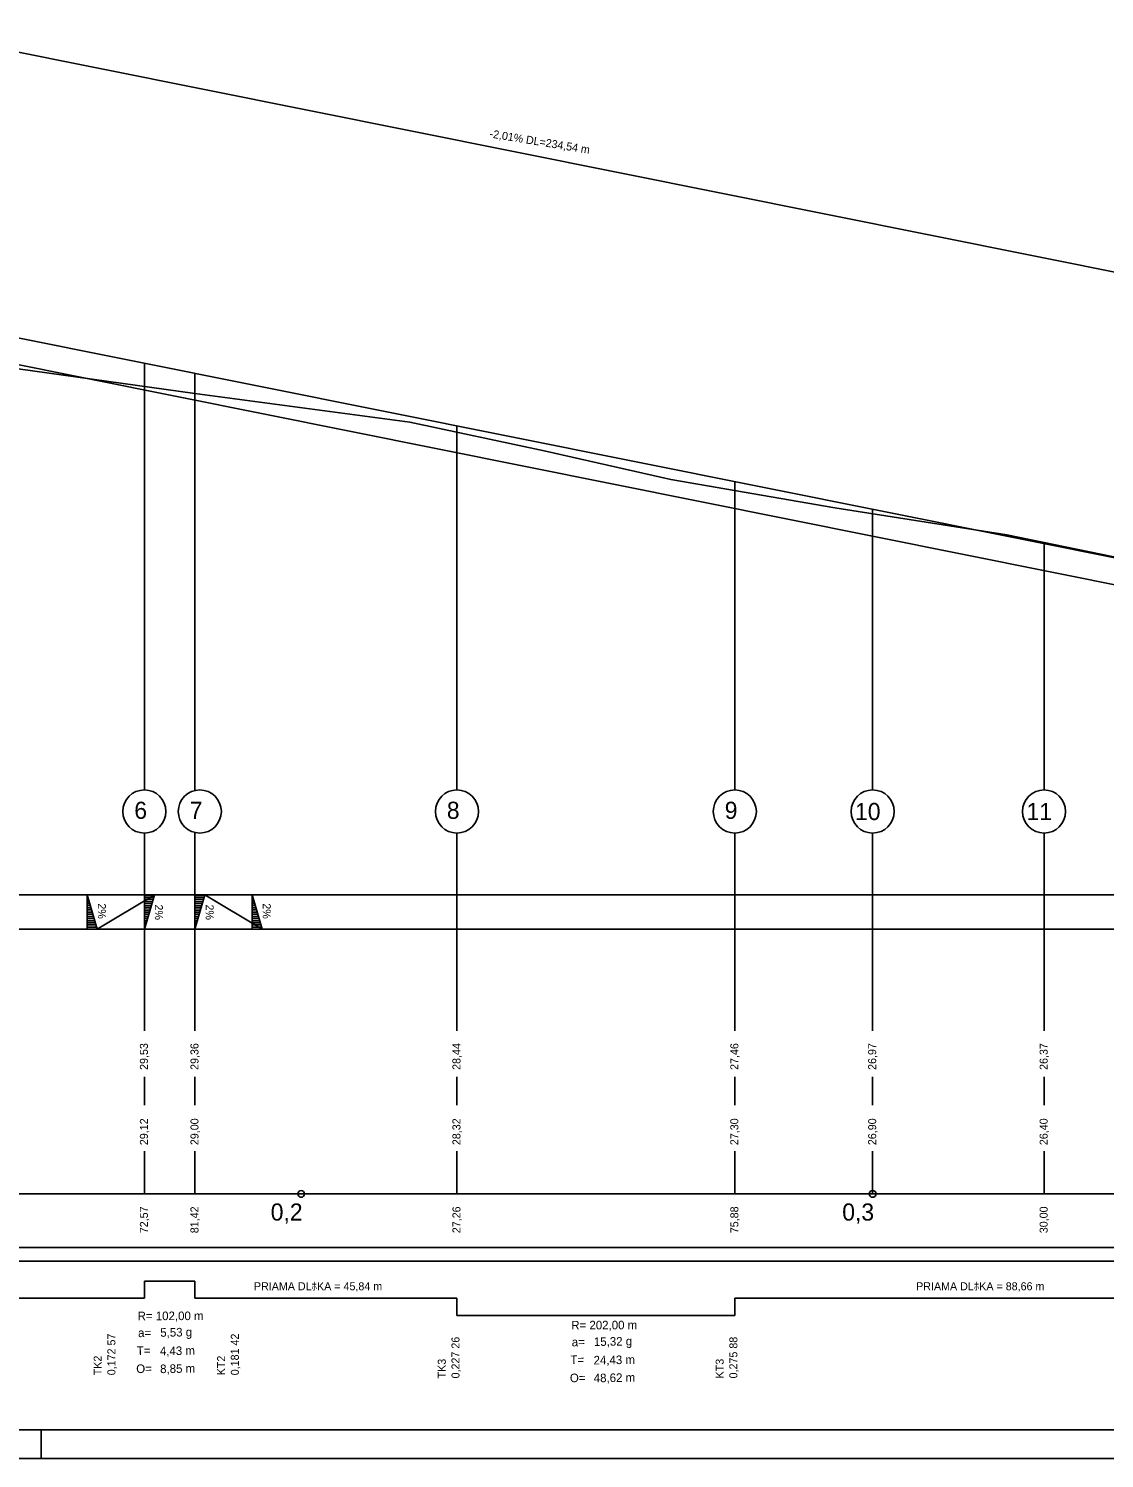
# Model space of a CAD drawing. Extents: x -499093 to -498463, y -1280289 to -1279879.
# Drawn here: x -498885.6 to -498697.4, y -1280289.4 to -1280039.2 of the extents above; entities that cross this region are included whole.
import ezdxf

# ---------------------------------------------------------------- set-up
doc = ezdxf.new("R2010")
doc.units = 0
for name, color, linetype in [('Vrstva 1', 7, 'Continuous'), ('Vrstva 11', 7, 'Continuous'), ('Vrstva 12', 7, 'Continuous'), ('Vrstva 13', 7, 'Continuous'), ('Vrstva 4', 7, 'Continuous'), ('Vrstva 5', 7, 'Continuous'), ('Vrstva 8', 7, 'Continuous')]:
    doc.layers.add(name, color=color, linetype=linetype)

msp = doc.modelspace()

# ---------------------------------------------------------------- linework, layer by layer
at = {"layer": 'Vrstva 1'}
for p, q in [((-499088.41, -1280284.38), (-498468.41, -1280284.38)), ((-498883.41, -1280284.38), (-498883.41, -1280289.38)), ((-499093.41, -1280289.38), (-498463.41, -1280289.38))]:
    msp.add_line(p, q, dxfattribs=at)
at = {"layer": 'Vrstva 11'}
for p, q in [((-498673.41, -1280136.31), (-498889.57, -1280092.93)), ((-498875.27, -1280191.18), (-498875.38, -1280191.18)), ((-498875.16, -1280191.56), (-498875.38, -1280191.56)), ((-498875.05, -1280191.93), (-498875.38, -1280191.93)), ((-498874.94, -1280192.31), (-498875.38, -1280192.31)), ((-498873.63, -1280196.81), (-498863.63, -1280190.81)), ((-498863.63, -1280190.82), (-498865.38, -1280190.82)), ((-498863.74, -1280191.2), (-498865.38, -1280191.2)), ((-498863.85, -1280191.57), (-498865.38, -1280191.57)), ((-498863.96, -1280191.95), (-498865.38, -1280191.95)), ((-498864.07, -1280192.32), (-498865.38, -1280192.32)), ((-498854.78, -1280190.82), (-498856.53, -1280190.82)), ((-498854.89, -1280191.2), (-498856.53, -1280191.2)), ((-498855, -1280191.57), (-498856.53, -1280191.57)), ((-498855.11, -1280191.95), (-498856.53, -1280191.95)), ((-498855.22, -1280192.32), (-498856.53, -1280192.32)), ((-498854.78, -1280190.81), (-498844.78, -1280196.81)), ((-498846.42, -1280191.18), (-498846.53, -1280191.18)), ((-498846.31, -1280191.56), (-498846.53, -1280191.56)), ((-498846.2, -1280191.93), (-498846.53, -1280191.93)), ((-498846.09, -1280192.31), (-498846.53, -1280192.31)), ((-498874.83, -1280192.68), (-498875.38, -1280192.68)), ((-498874.72, -1280193.06), (-498875.38, -1280193.06)), ((-498874.61, -1280193.43), (-498875.38, -1280193.43)), ((-498874.5, -1280193.81), (-498875.38, -1280193.81)), ((-498874.39, -1280194.18), (-498875.38, -1280194.18)), ((-498874.29, -1280194.56), (-498875.38, -1280194.56)), ((-498874.18, -1280194.93), (-498875.38, -1280194.93)), ((-498864.18, -1280192.7), (-498865.38, -1280192.7)), ((-498864.29, -1280193.07), (-498865.38, -1280193.07)), ((-498864.39, -1280193.45), (-498865.38, -1280193.45)), ((-498864.5, -1280193.82), (-498865.38, -1280193.82)), ((-498864.61, -1280194.2), (-498865.38, -1280194.2)), ((-498864.72, -1280194.57), (-498865.38, -1280194.57)), ((-498864.83, -1280194.95), (-498865.38, -1280194.95)), ((-498855.33, -1280192.7), (-498856.53, -1280192.7)), ((-498855.44, -1280193.07), (-498856.53, -1280193.07)), ((-498855.54, -1280193.45), (-498856.53, -1280193.45)), ((-498855.65, -1280193.82), (-498856.53, -1280193.82)), ((-498855.76, -1280194.2), (-498856.53, -1280194.2)), ((-498855.87, -1280194.57), (-498856.53, -1280194.57)), ((-498855.98, -1280194.95), (-498856.53, -1280194.95)), ((-498845.98, -1280192.68), (-498846.53, -1280192.68)), ((-498845.87, -1280193.06), (-498846.53, -1280193.06)), ((-498845.76, -1280193.43), (-498846.53, -1280193.43)), ((-498845.65, -1280193.81), (-498846.53, -1280193.81)), ((-498845.54, -1280194.18), (-498846.53, -1280194.18)), ((-498845.44, -1280194.56), (-498846.53, -1280194.56)), ((-498845.33, -1280194.93), (-498846.53, -1280194.93)), ((-498874.07, -1280195.31), (-498875.38, -1280195.31)), ((-498873.96, -1280195.68), (-498875.38, -1280195.68)), ((-498873.85, -1280196.06), (-498875.38, -1280196.06)), ((-498873.74, -1280196.43), (-498875.38, -1280196.43)), ((-498873.63, -1280196.81), (-498875.38, -1280196.81)), ((-498864.94, -1280195.32), (-498865.38, -1280195.32)), ((-498865.05, -1280195.7), (-498865.38, -1280195.7)), ((-498865.16, -1280196.07), (-498865.38, -1280196.07)), ((-498865.27, -1280196.45), (-498865.38, -1280196.45)), ((-498856.09, -1280195.32), (-498856.53, -1280195.32)), ((-498856.2, -1280195.7), (-498856.53, -1280195.7)), ((-498856.31, -1280196.07), (-498856.53, -1280196.07)), ((-498856.42, -1280196.45), (-498856.53, -1280196.45)), ((-498845.22, -1280195.31), (-498846.53, -1280195.31)), ((-498845.11, -1280195.68), (-498846.53, -1280195.68)), ((-498845, -1280196.06), (-498846.53, -1280196.06)), ((-498844.89, -1280196.43), (-498846.53, -1280196.43)), ((-498844.78, -1280196.81), (-498846.53, -1280196.81)), ((-499036.78, -1280243.11), (-498703.7, -1280243.11)), ((-499036.78, -1280243.11), (-498703.7, -1280243.11))]:
    msp.add_line(p, q, dxfattribs=at)
for points in [[(-498875.38, -1280196.81), (-498875.38, -1280190.81), (-498873.63, -1280196.81), (-498875.38, -1280196.81)], [(-498865.38, -1280190.81), (-498865.38, -1280196.81), (-498863.63, -1280190.81), (-498865.38, -1280190.81)], [(-498856.53, -1280190.81), (-498856.53, -1280196.81), (-498854.78, -1280190.81), (-498856.53, -1280190.81)], [(-498846.53, -1280196.81), (-498846.53, -1280190.81), (-498844.78, -1280196.81), (-498846.53, -1280196.81)]]:
    msp.add_lwpolyline(points, dxfattribs=at)
for centre in [(-498865.38, -1280176.21), (-498855.68, -1280176.21), (-498810.69, -1280176.21), (-498762.07, -1280176.21), (-498737.95, -1280176.21), (-498707.95, -1280176.21)]:
    msp.add_circle(centre, 3.77, dxfattribs=at)
at = {"layer": 'Vrstva 13'}
for p, q in [((-498673.41, -1280086.31), (-498907.95, -1280039.25)), ((-498889.95, -1280098.41), (-498856.53, -1280103.11)), ((-498865.38, -1280097.79), (-498865.38, -1280172.45)), ((-498856.53, -1280099.56), (-498856.53, -1280172.55)), ((-498856.53, -1280103.11), (-498818.95, -1280108.11)), ((-498818.95, -1280108.11), (-498795.45, -1280113.11)), ((-498810.69, -1280108.76), (-498810.69, -1280172.45)), ((-498795.45, -1280113.11), (-498773.26, -1280118.11)), ((-498773.26, -1280118.11), (-498744.59, -1280123.11)), ((-498762.07, -1280118.52), (-498762.07, -1280172.45)), ((-498744.59, -1280123.11), (-498714.45, -1280127.81)), ((-498737.95, -1280123.36), (-498737.95, -1280172.45)), ((-498714.45, -1280127.81), (-498673.41, -1280136.31)), ((-498707.95, -1280129.16), (-498707.95, -1280172.45)), ((-498865.38, -1280179.98), (-498865.38, -1280214.61)), ((-498856.53, -1280179.88), (-498856.53, -1280214.61)), ((-498810.69, -1280179.98), (-498810.69, -1280214.61)), ((-498762.07, -1280179.98), (-498762.07, -1280214.61)), ((-498737.95, -1280179.98), (-498737.95, -1280214.61)), ((-498707.95, -1280179.98), (-498707.95, -1280214.61)), ((-499037.95, -1280190.81), (-498673.41, -1280190.81)), ((-499037.95, -1280196.81), (-498673.41, -1280196.81)), ((-498865.38, -1280222.61), (-498865.38, -1280227.61)), ((-498856.53, -1280222.61), (-498856.53, -1280227.61)), ((-498810.69, -1280222.61), (-498810.69, -1280227.61)), ((-498762.07, -1280222.61), (-498762.07, -1280227.61)), ((-498737.95, -1280222.61), (-498737.95, -1280227.61)), ((-498707.95, -1280222.61), (-498707.95, -1280227.61)), ((-498865.38, -1280235.61), (-498865.38, -1280243.11)), ((-498856.53, -1280235.61), (-498856.53, -1280243.11)), ((-498810.69, -1280235.61), (-498810.69, -1280243.11)), ((-498762.07, -1280235.61), (-498762.07, -1280243.11)), ((-498737.95, -1280235.61), (-498737.95, -1280243.11)), ((-498707.95, -1280235.61), (-498707.95, -1280243.11))]:
    msp.add_line(p, q, dxfattribs=at)
for centre in [(-498837.95, -1280243.11), (-498737.95, -1280243.11)]:
    msp.add_circle(centre, 0.592, dxfattribs=at)
at = {"layer": 'Vrstva 8'}
for p, q in [((-498673.41, -1280141), (-498890.47, -1280097.44)), ((-499036.78, -1280243.11), (-498673.41, -1280243.11)), ((-499037.95, -1280252.46), (-498673.41, -1280252.46)), ((-499037.95, -1280254.86), (-498673.41, -1280254.86)), ((-498865.38, -1280261.36), (-498865.38, -1280258.36)), ((-498865.38, -1280258.36), (-498856.53, -1280258.36)), ((-498856.53, -1280261.36), (-498856.53, -1280258.36)), ((-498977.55, -1280261.36), (-498865.38, -1280261.36)), ((-498856.53, -1280261.36), (-498810.69, -1280261.36)), ((-498810.69, -1280264.36), (-498810.69, -1280261.36)), ((-498762.07, -1280264.36), (-498762.07, -1280261.36)), ((-498762.07, -1280261.36), (-498673.41, -1280261.36)), ((-498810.69, -1280264.36), (-498762.07, -1280264.36))]:
    msp.add_line(p, q, dxfattribs=at)

# ---------------------------------------------------------------- texts
at = {"layer": 'Vrstva 12'}
for s, height, p in [('6', 3, (-498867.14, -1280177.5)), ('7', 3, (-498857.44, -1280177.5)), ('8', 3, (-498812.45, -1280177.5)), ('9', 3, (-498763.83, -1280177.5)), ('10', 3, (-498741.03, -1280177.71)), ('11', 3, (-498711.03, -1280177.71)), ('0,2', 3, (-498843.27, -1280247.78)), ('0,3', 3, (-498743.27, -1280247.78)), ('PRIAMA DLﾎKA = 45,84 m', 1.4, (-498846.21, -1280259.97)), ('PRIAMA DLﾎKA = 88,66 m', 1.4, (-498730.34, -1280259.97))]:
    msp.add_text(s, height=height, dxfattribs=at).set_placement(p)
for s, rotation, p in [('2%', 270, (-498873.51, -1280192.28)), ('2%', 270, (-498863.54, -1280192.48)), ('2%', 270, (-498854.65, -1280192.48)), ('2%', 270, (-498844.66, -1280192.28)), ('29,53', 90, (-498864.76, -1280221.42)), ('29,36', 90, (-498855.91, -1280221.42)), ('28,44', 90, (-498810.07, -1280221.42)), ('27,46', 90, (-498761.45, -1280221.42)), ('26,97', 90, (-498737.33, -1280221.42)), ('26,37', 90, (-498707.33, -1280221.42)), ('29,12', 90, (-498864.76, -1280234.58)), ('29,00', 90, (-498855.91, -1280234.58)), ('28,32', 90, (-498810.07, -1280234.58)), ('27,30', 90, (-498761.45, -1280234.58)), ('26,90', 90, (-498737.33, -1280234.58)), ('26,40', 90, (-498707.33, -1280234.58)), ('72,57', 90, (-498864.76, -1280249.99)), ('81,42', 90, (-498855.91, -1280249.99)), ('27,26', 90, (-498810.07, -1280249.99)), ('75,88', 90, (-498761.45, -1280249.99)), ('30,00', 90, (-498707.33, -1280249.99)), ('0,172 57', 90, (-498870.45, -1280274.84)), ('0,181 42', 90, (-498848.85, -1280274.84)), ('0,227 26', 90, (-498810.24, -1280275.39)), ('0,275 88', 90, (-498761.62, -1280275.39)), ('TK2', 90, (-498872.85, -1280274.84)), ('KT2', 90, (-498851.25, -1280274.84)), ('TK3', 90, (-498812.64, -1280275.39)), ('KT3', 90, (-498764.02, -1280275.39))]:
    msp.add_text(s, height=1.4, rotation=rotation, dxfattribs=at).set_placement(p)
at = {"layer": 'Vrstva 4'}
msp.add_text('-2,01% DL=234,54 m', height=1.4, rotation=350.63, dxfattribs=at).set_placement((-498805.06, -1280058.27))
at = {"layer": 'Vrstva 5'}
for s, rotation, p in [('R= 102,00 m', 0.1235, (-498866.56, -1280265.21)), ('a=', 0.9266, (-498866.47, -1280268.17)), ('5,53 g', 0.9266, (-498862.59, -1280268.11)), ('R= 202,00 m', 0.1235, (-498790.68, -1280266.82)), ('T=', 0.9266, (-498866.69, -1280271.28)), ('4,43 m', 0.9266, (-498862.65, -1280271.35)), ('a=', 0.9266, (-498790.59, -1280269.78)), ('15,32 g', 0.9266, (-498786.71, -1280269.72)), ('T=', 0.9266, (-498790.82, -1280272.89)), ('24,43 m', 0.9266, (-498786.77, -1280272.96)), ('O=', 0.9266, (-498866.79, -1280274.45)), ('8,85 m', 0.9266, (-498862.61, -1280274.47)), ('O=', 0.9266, (-498790.91, -1280276.06)), ('48,62 m', 0.9266, (-498786.74, -1280276.08))]:
    msp.add_text(s, height=1.5, rotation=rotation, dxfattribs=at).set_placement(p)

doc.saveas('drawing.dxf')
